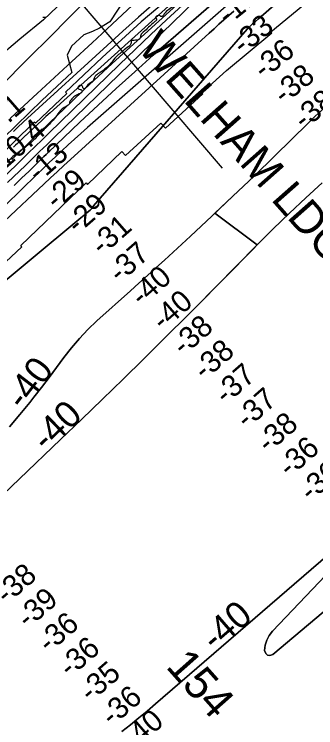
# Model space of a CAD drawing. Extents: x 3445503 to 3483459, y 540493 to 566012.
# Drawn here: x 3451887 to 3452821, y 547209 to 549421 of the extents above; entities that cross this region are included whole.
import ezdxf

# ---------------------------------------------------------------- set-up
doc = ezdxf.new("R2010")
doc.units = 0
for name, color, linetype in [('V-RIVR-EDGE', 7, 'Continuous'), ('V-RIVR-IDEN', 7, 'Continuous'), ('V-RIVR-RANG', 7, 'Continuous'), ('V-RRAP-RVMT', 7, 'Continuous'), ('V-SITE-VEGE', 7, 'Continuous'), ('V-TOPO-DPTH', 7, 'Continuous'), ('V-TOPO-GNAM-IDEN', 7, 'Continuous'), ('V-TOPO-MINR', 7, 'Continuous'), ('V-TOPO-MINR-IDEN', 7, 'Continuous'), ('V-TOPO-WATR', 7, 'Continuous'), ('V-WETL-SWMP', 7, 'Continuous')]:
    doc.layers.add(name, color=color, linetype=linetype)

msp = doc.modelspace()

# ---------------------------------------------------------------- linework, layer by layer
at = {"layer": 'V-RIVR-EDGE'}
for points in [[(3452565, 549632.1), (3452565.8, 549625.9), (3452563.7, 549618.5), (3452554.6, 549606.1), (3452547.2, 549600.4), (3452538.9, 549595.9), (3452524.5, 549586.4), (3452523.6, 549582.7), (3452524.4, 549578.2), (3452515.8, 549570.4), (3452499.6, 549558.9), (3452491, 549550.6), (3452475.2, 549530), (3452462.9, 549521.8), (3452457.1, 549517.3), (3452450, 549512.4), (3452445.1, 549511.1), (3452443.9, 549509.1), (3452445.1, 549506.2), (3452435.2, 549495.9), (3452420.7, 549482.3), (3452414.1, 549476.2), (3452409.5, 549472.9), (3452405.8, 549470), (3452404.2, 549467.9), (3452400, 549461.4), (3452394.6, 549457.7), (3452387.6, 549454.8), (3452379.8, 549447), (3452351.7, 549422.3), (3452344.2, 549414.5), (3452341.3, 549414.5), (3452336.8, 549417.4), (3452332.7, 549417.4), (3452327.3, 549414.9), (3452324.8, 549411.6), (3452327.3, 549406.3), (3452327.3, 549403), (3452324.8, 549400.1), (3452317.4, 549393.9), (3452303.3, 549381.2), (3452286.8, 549365.5), (3452278.9, 549356.5), (3452277.7, 549350.3), (3452273.1, 549342.9), (3452262.8, 549340.4), (3452255, 549340.1), (3452250.4, 549338.8), (3452249.6, 549334.7), (3452248.7, 549329.8), (3452231.8, 549314.1), (3452217.3, 549301.4), (3452203.7, 549290.3), (3452185.5, 549268.1), (3452173.5, 549256.1), (3452162.4, 549247.1), (3452149.5, 549238.5), (3452142.5, 549233.5), (3452138, 549229), (3452135.9, 549224.9), (3452133.8, 549220.3), (3452131.3, 549214.6), (3452114.8, 549202.2), (3452102.4, 549190.3), (3452100.8, 549191.1), (3452097.5, 549199), (3452094.6, 549200.6), (3452086.8, 549198.2), (3452084.3, 549194.5), (3452084.3, 549192.8), (3452086.3, 549189.5), (3452095.4, 549186.6), (3452097.4, 549183.3), (3452082.6, 549171.8), (3452071.8, 549165.2), (3452060.3, 549152.5), (3452058.2, 549147.9), (3452057.8, 549143.8), (3452047.4, 549135.6), (3452010.6, 549096.9), (3451980, 549064.4), (3451955.2, 549038.5), (3451925, 549011.8)], [(3451925, 549011.8), (3451906.9, 548998.2), (3451896.5, 548990.8), (3451890.8, 548986.7), (3451875, 548972.3), (3451838.7, 548937.3), (3451815.1, 548916.8), (3451777.1, 548879.3), (3451754.8, 548857.1), (3451741.5, 548843.5), (3451725, 548828.3), (3451716.7, 548821.8), (3451713.4, 548821.3), (3451708.1, 548820.5), (3451704.7, 548816.8), (3451702.3, 548810.7), (3451684.1, 548789.3), (3451651.8, 548755.1), (3451627.4, 548730.8), (3451620, 548725.9), (3451613.8, 548725.5), (3451610.9, 548724.7), (3451608.8, 548722.6), (3451607.2, 548720.2), (3451606.3, 548711.9), (3451594.3, 548698.7), (3451584.8, 548688), (3451576.6, 548684.4), (3451565.8, 548677), (3451549.7, 548663), (3451524.5, 548637.9), (3451489.4, 548604.6), (3451461.7, 548579.1), (3451446.4, 548566.7), (3451433.6, 548556.9), (3451415.8, 548544.5), (3451408.4, 548537.9), (3451388.9, 548508.7), (3451359.9, 548468.4), (3451343, 548449), (3451327.3, 548433.4), (3451287.2, 548395.6), (3451273.9, 548379.5), (3451265.2, 548366.7), (3451258.2, 548357.3), (3451242.1, 548340), (3451208.6, 548307.1), (3451174.3, 548272.9), (3451127.1, 548222.3), (3451103.6, 548199.3), (3451092.8, 548191.1), (3451087.9, 548184.5), (3451081.7, 548175), (3451074.6, 548169.3), (3451066.4, 548163.1), (3451063.9, 548161), (3451061.4, 548154.9), (3451056.4, 548150.7), (3451049, 548144.2), (3451044.4, 548135.5), (3451038.6, 548125.6), (3451024.6, 548112.9), (3450996.9, 548090.7), (3450984.1, 548083.7), (3450968.4, 548079.6), (3450953.2, 548075.9), (3450948.2, 548073.1), (3450944.5, 548064.4), (3450943.2, 548062.4), (3450938.7, 548062.4), (3450937, 548059.9), (3450933.3, 548054.1), (3450926.3, 548049.6), (3450919.3, 548045.5), (3450916.4, 548042.6), (3450913.1, 548038.5), (3450907.7, 548036), (3450903.1, 548031.9), (3450898.6, 548027.4), (3450884.5, 548004.3), (3450877.5, 547990.3), (3450865.4, 547964), (3450858.4, 547953.3), (3450851.4, 547947.1), (3450846.4, 547943.8), (3450841.1, 547938.9), (3450836.9, 547933.9), (3450834, 547925.3), (3450830.3, 547920.8), (3450813.8, 547915.4), (3450791.5, 547902.3), (3450765.8, 547879.3), (3450757.2, 547871.9), (3450751.4, 547869.4), (3450748.5, 547869.8), (3450740.7, 547868.2), (3450728.7, 547857.1), (3450719.2, 547846.4), (3450715.4, 547842.7), (3450714.6, 547838.6), (3450712.5, 547834.9), (3450698.5, 547818.8), (3450679.9, 547799.1), (3450660, 547778.1), (3450655.5, 547773.1), (3450650.1, 547771.5), (3450644.3, 547771.5), (3450637.3, 547769.5), (3450622.4, 547753.8), (3450615, 547744.8), (3450605.5, 547736.6), (3450602.2, 547731.2), (3450596.8, 547715.1), (3450588.9, 547703.6), (3450582.7, 547699.9), (3450577.7, 547695.4), (3450564.1, 547681), (3450557.1, 547676.5), (3450549.2, 547672), (3450543.4, 547662.9), (3450538.5, 547651.8), (3450535.6, 547646), (3450535.1, 547638.6), (3450535.1, 547625), (3450533.4, 547618), (3450525.2, 547607.7), (3450500.3, 547578), (3450469.7, 547546.4), (3450444.9, 547518.8), (3450425.9, 547499.5), (3450395.3, 547464.5), (3450367.6, 547435.3), (3450339.1, 547404.8), (3450310.1, 547376.8), (3450301.5, 547370.3), (3450296.9, 547367.8), (3450289, 547356.7), (3450281.2, 547345.6), (3450275.8, 547338.6), (3450270.4, 547336.9), (3450265.1, 547332), (3450258.9, 547327.5), (3450246.1, 547318.4), (3450231.2, 547298.3), (3450212.1, 547275.6), (3450187.7, 547248.1), (3450160.9, 547218.4), (3450144.7, 547202.4), (3450126.5, 547184.3), (3450110, 547166.2), (3450091, 547148.1), (3450072.4, 547127.9), (3450049.6, 547104.1), (3450015.3, 547069.9), (3449993, 547047.3), (3449946.7, 546988.4), (3449899.5, 546934.9), (3449866.9, 546902), (3449840.4, 546865.8), (3449803.6, 546824.6), (3449770.9, 546786), (3449751, 546765.4), (3449725.8, 546739.9), (3449714.2, 546724.2), (3449695.6, 546703.3), (3449687.3, 546690.9), (3449677.4, 546669.1), (3449668.7, 546652.2), (3449652.1, 546629.9), (3449646.3, 546622.3)]]:
    msp.add_spline(points, degree=3, dxfattribs=at)
at = {"layer": 'V-RIVR-RANG'}
msp.add_line((3451920.2, 549659), (3452531, 548944.4), dxfattribs=at)
at = {"layer": 'V-RRAP-RVMT'}
for points in [[(3452849, 549870.1), (3452722.2, 549777.5), (3452723.4, 549775.4), (3452601.8, 549682.7), (3452605, 549678), (3452489.5, 549581.7), (3452494.3, 549574.9), (3452383.1, 549485.4), (3452279.9, 549397.3), (3452159.3, 549286.7), (3452045.7, 549179.8), (3452049.8, 549175.4), (3451952.3, 549083.3), (3451948.9, 549086.9), (3451634.9, 548778.5), (3451629.3, 548784.2), (3451526.3, 548680), (3451519.2, 548687), (3451409, 548577.8), (3451416.2, 548570.4), (3451308.4, 548461.2), (3451314.5, 548454.8), (3451170.4, 548312.5), (3450996.6, 548124.9)], [(3451795.2, 548592.7), (3451910.6, 548699.9), (3451907.2, 548704), (3452109.3, 548898.4), (3452114, 548893.7), (3452220, 548995.4), (3452231.6, 548983.5), (3452341.2, 549083.6), (3452355.7, 549067.6), (3452471.5, 549174), (3452468.6, 549177.6), (3452544.5, 549247.3), (3452684.8, 549364), (3452682.5, 549366.9), (3452781.4, 549448.2)]]:
    msp.add_lwpolyline(points, dxfattribs=at)
at = {"layer": 'V-SITE-VEGE'}
msp.add_lwpolyline([(3452229.1, 549467.5), (3452183.2, 549397.4), (3452150.8, 549378.5), (3452129.3, 549367.7), (3452102.3, 549356.9), (3452064.5, 549321.8), (3452051, 549294.8), (3452065.3, 549240.7), (3451973.5, 549154.4), (3451852.5, 549036.7)], dxfattribs=at)
at = {"layer": 'V-TOPO-DPTH'}
for points in [[(3453098.1, 549804.2), (3452643.4, 549406.7), (3452634.5, 549399), (3452625.8, 549391.1), (3452617.1, 549383.2), (3452608.4, 549375.3), (3452132.1, 548826.6), (3452131, 548824.9), (3452129.6, 548822.2), (3452127.9, 548819.7), (3452124.4, 548815.6), (3452123.3, 548814.3), (3452122.7, 548813.8), (3452122, 548813.2), (3452113.2, 548806.1), (3452108.1, 548802.1), (3452103.1, 548798), (3452098, 548793.8), (3452093, 548789.7), (3451451.5, 548256.9)], [(3451451.5, 548256.9), (3452093, 548789.7), (3452098, 548793.8), (3452103.1, 548798), (3452108.1, 548802.1), (3452113.2, 548806.1), (3452122, 548813.2), (3452122.7, 548813.8), (3452123.3, 548814.3), (3452124.4, 548815.6), (3452127.9, 548819.7), (3452129.6, 548822.2), (3452131, 548824.9), (3452132.1, 548826.6), (3452608.4, 549375.3), (3452617.1, 549383.2), (3452625.8, 549391.1), (3452634.5, 549399), (3452643.4, 549406.7), (3453098.1, 549804.2)], [(3452460, 549533.4), (3451997.9, 549115.5), (3451985.2, 549103.9), (3451972.5, 549092.2), (3451959.8, 549080.5), (3451947.2, 549068.7), (3451925.4, 549048.2), (3451923.7, 549046.7), (3451922.1, 549045.1), (3451918.8, 549042), (3451909.4, 549033.1), (3451903.1, 549027), (3451896.9, 549020.9), (3451890.7, 549014.8), (3451884.5, 549008.6)], [(3451886.2, 548890), (3451909.4, 548912.4), (3451932.7, 548934.9), (3451966.2, 548967.3), (3451972.6, 548973.6), (3451979.1, 548979.8), (3451985.5, 548985.9), (3451992, 548992.1), (3452090.4, 549086.2), (3452146.5, 549139.1), (3452203, 549191.4), (3452260.3, 549243), (3452317.9, 549294.1), (3452505.1, 549457.4)], [(3451886.2, 548890), (3451909.4, 548912.4), (3451932.7, 548934.9), (3451966.2, 548967.3), (3451972.6, 548973.6), (3451979.1, 548979.8), (3451985.5, 548985.9), (3451992, 548992.1), (3452090.4, 549086.2), (3452146.5, 549139.1), (3452203, 549191.4), (3452260.3, 549243), (3452317.9, 549294.1), (3452505.1, 549457.4)], [(3452408.3, 549449.1), (3452359.1, 549403.9), (3452310.2, 549358.2), (3452261.7, 549312.2), (3452213.6, 549265.8), (3451994.3, 549052.5), (3451973, 549031.8), (3451951.7, 549011.1), (3451930.4, 548990.4), (3451909.1, 548969.6), (3451801.2, 548864.6)], [(3451801.2, 548864.6), (3451909.1, 548969.6), (3451930.4, 548990.4), (3451951.7, 549011.1), (3451973, 549031.8), (3451994.3, 549052.5), (3452213.6, 549265.8), (3452261.7, 549312.2), (3452310.2, 549358.2), (3452359.1, 549403.9), (3452408.3, 549449.1)], [(3452567.4, 549431.1), (3452552, 549417.5), (3452536.7, 549403.8), (3452521.3, 549390.1), (3452506.1, 549376.3), (3452490.8, 549362.5), (3452061.1, 548971), (3452040.4, 548952.1), (3452019.8, 548933), (3451999.3, 548913.9), (3451978.8, 548894.7), (3451858, 548780.6)], [(3451858, 548780.6), (3451978.8, 548894.7), (3451999.3, 548913.9), (3452019.8, 548933), (3452040.4, 548952.1), (3452061.1, 548971), (3452490.8, 549362.5), (3452506.1, 549376.3), (3452521.3, 549390.1), (3452536.7, 549403.8), (3452552, 549417.5), (3452567.4, 549431.1)], [(3452839.8, 549124.1), (3452818.9, 549103.8), (3452798.2, 549083.5), (3452694.9, 548982.2), (3452630.1, 548919.3), (3452564.8, 548856.7), (3452499, 548794.7), (3452432.8, 548733.2), (3452352.1, 548658.9), (3452325.9, 548634.9), (3452299.6, 548610.9), (3452273.3, 548587), (3452246.9, 548563.2), (3452142.8, 548470), (3452115.2, 548443.5), (3452088.7, 548415.9), (3452064.1, 548386.6), (3452040.7, 548356.3), (3452018.1, 548325.3), (3451995.1, 548294.5), (3451971.7, 548264), (3451948.1, 548233.8), (3451935, 548217.4), (3451904.1, 548179.5), (3451872.6, 548142.2)], [(3452640, 548706.1), (3452508.8, 548803.9), (3452564.8, 548856.7), (3452630.1, 548919.3), (3452694.9, 548982.2), (3452798.2, 549083.5), (3452818.9, 549103.8), (3452839.8, 549124.1)], [(3451491.6, 547070.7), (3451737.8, 547821.1), (3451747, 547830.6), (3451756.3, 547840), (3451765.8, 547849.4), (3451775.3, 547858.6), (3452030.7, 548102.6), (3452095.5, 548164.7), (3452160, 548227.1), (3452224.1, 548289.8), (3452288.1, 548352.8), (3452382.6, 548446.3), (3452399.1, 548462.7), (3452415.5, 548479.1), (3452432, 548495.6), (3452448.3, 548512.1), (3452640, 548706.1), (3452689.4, 548755.3), (3452739.5, 548803.9), (3452790.3, 548851.6), (3452841.7, 548898.8)], [(3452841.7, 548898.8), (3452790.3, 548851.6), (3452739.5, 548803.9), (3452689.4, 548755.3), (3452640, 548706.1)], [(3451872.6, 548142.2), (3451904.1, 548179.5), (3451935, 548217.4), (3451948.1, 548233.8), (3451971.7, 548264), (3451995.1, 548294.5), (3452018.1, 548325.3), (3452040.7, 548356.3), (3452064.1, 548386.6), (3452088.7, 548415.9), (3452115.2, 548443.5), (3452142.8, 548470), (3452246.9, 548563.2), (3452273.3, 548587), (3452299.6, 548610.9), (3452325.9, 548634.9), (3452352.1, 548658.9), (3452432.8, 548733.2), (3452499, 548794.7), (3452508.8, 548803.9), (3452640, 548706.1), (3452627.2, 548693.2)], [(3452627.2, 548693.2), (3452448.3, 548512.1), (3452432, 548495.6), (3452415.5, 548479.1), (3452399.1, 548462.7), (3452382.6, 548446.3), (3452288.1, 548352.8), (3452224.1, 548289.8), (3452160, 548227.1), (3452095.5, 548164.7), (3452030.7, 548102.6), (3451775.3, 547858.6), (3451765.8, 547849.4), (3451756.3, 547840), (3451747, 547830.6), (3451737.8, 547821.1), (3451491.6, 547070.7)], [(3453040.1, 547731.8), (3452688.6, 547435.6), (3452679.3, 547432.8), (3452671.6, 547433.4), (3452666.3, 547439.1), (3452662.6, 547448.1), (3452664.9, 547464.8), (3452669.5, 547480.6), (3452677.4, 547495), (3452687.6, 547508.5), (3452976, 547811.4)], [(3452976, 547811.4), (3452687.6, 547508.5), (3452677.4, 547495), (3452669.5, 547480.6), (3452664.9, 547464.8), (3452662.6, 547448.1), (3452666.3, 547439.1), (3452671.6, 547433.4), (3452679.3, 547432.8), (3452688.6, 547435.6), (3453040.1, 547731.8)], [(3452859.8, 547745.3), (3452324.9, 547282.4), (3452299.2, 547260.5), (3452273.2, 547238.9), (3452246.9, 547217.8), (3452220.4, 547196.9)], [(3452220.4, 547196.9), (3452246.9, 547217.8), (3452273.2, 547238.9), (3452299.2, 547260.5), (3452324.9, 547282.4), (3452859.8, 547745.3)]]:
    msp.add_lwpolyline(points, dxfattribs=at)
at = {"layer": 'V-TOPO-MINR'}
for points in [[(3453098.1, 549804.2), (3452643.4, 549406.7), (3452634.5, 549399), (3452625.8, 549391.1), (3452617.1, 549383.2), (3452608.4, 549375.3), (3452132.1, 548826.6), (3452131, 548824.9), (3452129.6, 548822.2), (3452127.9, 548819.7), (3452124.4, 548815.6), (3452123.3, 548814.3), (3452122.7, 548813.8), (3452122, 548813.2), (3452113.2, 548806.1), (3452108.1, 548802.1), (3452103.1, 548798), (3452098, 548793.8), (3452093, 548789.7), (3451451.5, 548256.9)], [(3452512.9, 549526.9), (3452009.6, 549038.2), (3451987.6, 549016.7), (3451965.5, 548995.3), (3451943.4, 548973.9), (3451921.3, 548952.5), (3451866.4, 548899.2)], [(3452479.5, 549531.8), (3452190.5, 549268.2), (3452147.7, 549228.8), (3452105.1, 549189.1), (3452063, 549148.9), (3452021.1, 549108.5), (3451995.6, 549083.6), (3451966.6, 549055.4), (3451937.7, 549027.2), (3451908.8, 548998.9), (3451879.9, 548970.7)], [(3452460, 549533.4), (3451997.9, 549115.5), (3451985.2, 549103.9), (3451972.5, 549092.2), (3451959.8, 549080.5), (3451947.2, 549068.7), (3451925.4, 549048.2), (3451923.7, 549046.7), (3451922.1, 549045.1), (3451918.8, 549042), (3451909.4, 549033.1), (3451903.1, 549027), (3451896.9, 549020.9), (3451890.7, 549014.8), (3451884.5, 549008.6)], [(3452552.1, 549453.2), (3452113.6, 549069.7), (3452093.6, 549051.9), (3452073.6, 549034.1), (3452053.9, 549016), (3452034.3, 548997.8), (3452014.8, 548979.4), (3451995.4, 548961), (3451976.1, 548942.4), (3451956.9, 548923.8), (3451615.6, 548591.4)], [(3451837.4, 549190.9), (3451935.7, 549288.9), (3451995.9, 549349.5), (3452055.9, 549410.3), (3452115.5, 549471.5)], [(3452321.8, 549455.4), (3452272.3, 549412.1), (3452223.3, 549368.4), (3452174.6, 549324.3), (3451928.3, 549099.2), (3451913.5, 549085.6), (3451898.7, 549071.9), (3451884.1, 549058.1)], [(3452505.1, 549457.4), (3452317.9, 549294.1), (3452260.3, 549243), (3452203, 549191.4), (3452146.5, 549139.1), (3452090.4, 549086.2), (3451992, 548992.1), (3451985.5, 548985.9), (3451979.1, 548979.8), (3451972.6, 548973.6), (3451966.2, 548967.3), (3451932.7, 548934.9), (3451909.4, 548912.4), (3451886.2, 548890)], [(3452567.4, 549431.1), (3452552, 549417.5), (3452536.7, 549403.8), (3452521.3, 549390.1), (3452506.1, 549376.3), (3452490.8, 549362.5), (3452061.1, 548971), (3452040.4, 548952.1), (3452019.8, 548933), (3451999.3, 548913.9), (3451978.8, 548894.7), (3451858, 548780.6)], [(3452253, 549448.9), (3452190.7, 549390.9), (3452128.2, 549333), (3452065.7, 549275.2), (3451931, 549150.8), (3451903, 549125), (3451875.1, 549099)], [(3451872.6, 548142.2), (3451904.1, 548179.5), (3451935, 548217.4), (3451948.1, 548233.8), (3451971.7, 548264), (3451995.1, 548294.5), (3452018.1, 548325.3), (3452040.7, 548356.3), (3452064.1, 548386.6), (3452088.7, 548415.9), (3452115.2, 548443.5), (3452142.8, 548470), (3452246.9, 548563.2), (3452273.3, 548587), (3452299.6, 548610.9), (3452325.9, 548634.9), (3452352.1, 548658.9), (3452432.8, 548733.2), (3452499, 548794.7), (3452564.8, 548856.7), (3452630.1, 548919.3), (3452694.9, 548982.2), (3452798.2, 549083.5), (3452818.9, 549103.8), (3452839.8, 549124.1)], [(3451491.6, 547070.7), (3451737.8, 547821.1), (3451747, 547830.6), (3451756.3, 547840), (3451765.8, 547849.4), (3451775.3, 547858.6), (3452030.7, 548102.6), (3452095.5, 548164.7), (3452160, 548227.1), (3452224.1, 548289.8), (3452288.1, 548352.8), (3452382.6, 548446.3), (3452399.1, 548462.7), (3452415.5, 548479.1), (3452432, 548495.6), (3452448.3, 548512.1), (3452640, 548706.1), (3452689.4, 548755.3), (3452739.5, 548803.9), (3452790.3, 548851.6), (3452841.7, 548898.8)], [(3453040.1, 547731.8), (3452688.6, 547435.6), (3452679.3, 547432.8), (3452671.6, 547433.4), (3452666.3, 547439.1), (3452662.6, 547448.1), (3452664.9, 547464.8), (3452669.5, 547480.6), (3452677.4, 547495), (3452687.6, 547508.5), (3452976, 547811.4)], [(3452859.8, 547745.3), (3452324.9, 547282.4), (3452299.2, 547260.5), (3452273.2, 547238.9), (3452246.9, 547217.8), (3452220.4, 547196.9)]]:
    msp.add_lwpolyline(points, dxfattribs=at)
at = {"layer": 'V-TOPO-WATR'}
msp.add_lwpolyline([(3452408.3, 549449.1), (3452359.1, 549403.9), (3452310.2, 549358.2), (3452261.7, 549312.2), (3452213.6, 549265.8), (3451994.3, 549052.5), (3451973, 549031.8), (3451951.7, 549011.1), (3451930.4, 548990.4), (3451909.1, 548969.6), (3451801.2, 548864.6)], dxfattribs=at)
at = {"layer": 'V-WETL-SWMP'}
msp.add_line((3451975, 549411.9), (3451986.2, 549411.9), dxfattribs=at)
msp.add_lwpolyline([(3452041.4, 549465.8), (3451977.8, 549403.7), (3451904.5, 549343.7), (3451827.3, 549280)], dxfattribs=at)

# ---------------------------------------------------------------- texts
at = {"layer": 'V-RIVR-IDEN'}
msp.add_text('154', height=100, rotation=311.5207, dxfattribs=at).set_placement((3452354.1, 547397))
at = {"layer": 'V-RIVR-RANG'}
for s, rotation, p in [('-18', 38.8436, (3452548.1, 549384)), ('-33', 38.8436, (3452595, 549293.4)), ('-36', 38.8436, (3452660, 549217.3)), ('-38', 38.8436, (3452722.1, 549139)), ('24.1', 40.9383, (3451793.4, 549015.5)), ('-38', 38.8436, (3452784.6, 549060.9)), ('10.4', 40.9383, (3451857.4, 548938.6)), ('-13', 41.2263, (3451961.9, 548896.4)), ('-29', 41.2263, (3452017.5, 548812.2)), ('-29', 41.2263, (3452083.2, 548736.8)), ('-31', 41.2263, (3452158.8, 548670.1)), ('-37', 41.2263, (3452213.8, 548585.4)), ('-40', 41.2263, (3452281.9, 548512.1)), ('-40', 41.2263, (3452347.6, 548436.7)), ('-38', 41.2263, (3452410.8, 548359.1)), ('-38', 41.2263, (3452476.5, 548283.7)), ('-37', 41.2263, (3452542.4, 548208.5)), ('-37', 41.2263, (3452608.1, 548133.1)), ('-38', 41.2263, (3452673.7, 548057.6)), ('-36', 41.2263, (3452739.8, 547982.6)), ('-36', 41.2263, (3452805.5, 547907.2)), ('-38', 40.8339, (3451863.2, 547589.1)), ('-39', 40.8339, (3451929, 547513.8)), ('-36', 40.8339, (3451994, 547437.9)), ('-36', 40.8339, (3452059.2, 547362)), ('-35', 40.8339, (3452123.2, 547285.2)), ('-36', 40.8339, (3452189.6, 547210.4)), ('-40', 40.8339, (3452257, 547136.5))]:
    msp.add_text(s, height=67, rotation=rotation, dxfattribs=at).set_placement(p)
at = {"layer": 'V-TOPO-GNAM-IDEN'}
msp.add_text('WELHAM LDG.', height=100, rotation=311.5134, dxfattribs=at).set_placement((3452266.6, 549313.9))
at = {"layer": 'V-TOPO-MINR-IDEN'}
for rotation, p in [(52.5002, (3451914.9, 548190)), (43.8375, (3451987.1, 548060.7)), (40.8752, (3452509.3, 547442))]:
    msp.add_text('-40', height=83, rotation=rotation, dxfattribs=at).set_placement(p)

doc.saveas('drawing.dxf')
